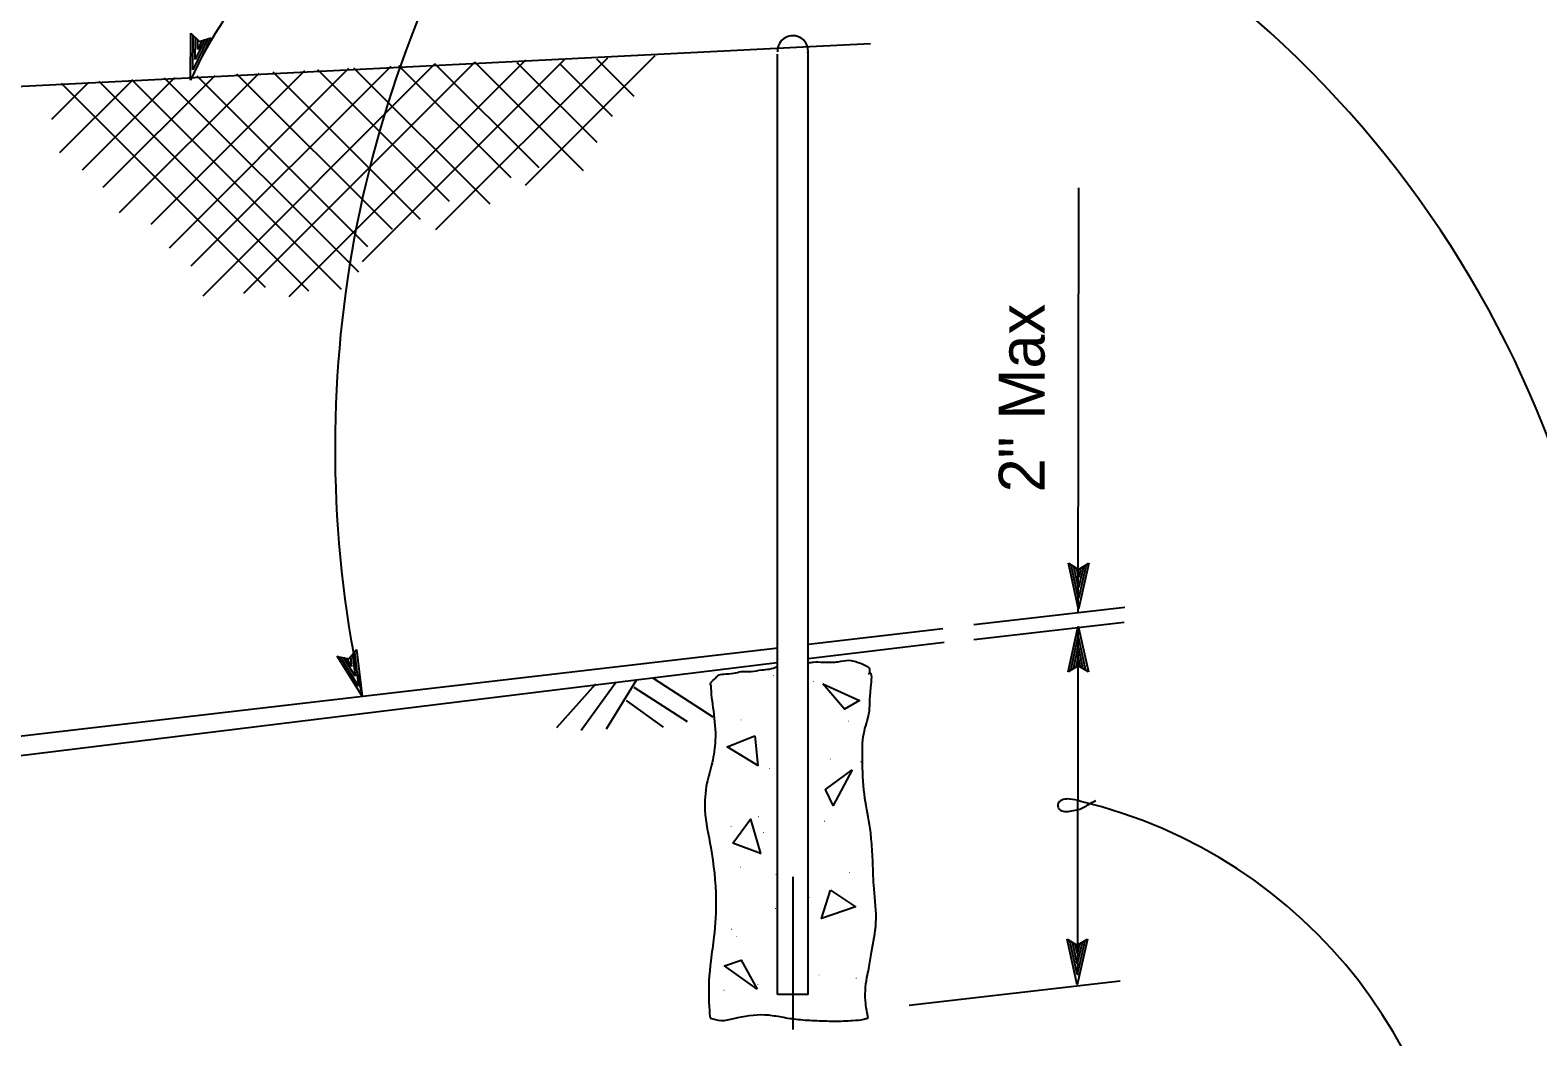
# Model space of a CAD drawing. Extents: x 6710407 to 6714861, y 1868090 to 1871317.
# Drawn here: x 6711941.5 to 6712138.9, y 1870342.8 to 1870474.7 of the extents above; entities that cross this region are included whole.
import ezdxf

# ---------------------------------------------------------------- set-up
doc = ezdxf.new("R2010")
doc.units = 0
for name, color, linetype in [('G-MARK', 7, 'Continuous'), ('G-TEXT', 7, 'Continuous'), ('Nongeo Data(60)', 7, 'Continuous')]:
    doc.layers.add(name, color=color, linetype=linetype)

msp = doc.modelspace()

# ---------------------------------------------------------------- linework, layer by layer
at = {"layer": 'G-MARK'}
for p, q in [((6712078.74, 1870398.4), (6712078.79, 1870454.09)), ((6712065.04, 1870396.85), (6712084.83, 1870399.15)), ((6712065.05, 1870394.89), (6712084.76, 1870397.18)), ((6712078.69, 1870350.91), (6712078.73, 1870396.57)), ((6712056.59, 1870346.99), (6712084.22, 1870350.2))]:
    msp.add_line(p, q, dxfattribs=at)
msp.add_lwpolyline([(6712041.34, 1870363.81), (6712041.34, 1870343.81)], dxfattribs=at)
for centre, radius, start, end in [((6712013, 1870445.19), 55.53, 98.9217, 155.5531), ((6712132.22, 1870419.98), 150.83, 147.9377, 192.4445), ((6712010.63, 1870371.44), 138.89, 1.0544, 66.3616), ((6712063.9, 1870310.34), 65.14, 358.9398, 76.5372)]:
    msp.add_arc(centre, radius, start, end, dxfattribs=at)
msp.add_spline([(6712079.07, 1870373.69), (6712077.59, 1870374), (6712076.75, 1870373.92), (6712076.17, 1870373.54), (6712076.09, 1870372.92), (6712076.26, 1870372.63), (6712076.92, 1870372.38), (6712077.88, 1870372.46), (6712078.75, 1870372.63), (6712079.46, 1870372.92), (6712080.16, 1870373.34), (6712081.04, 1870373.79)], degree=3, dxfattribs=at)
at = {"layer": 'G-TEXT'}
for p, q in [((6711962.46, 1870468.17), (6711962.52, 1870474.32)), ((6711962.52, 1870474.32), (6711962.52, 1870474.32)), ((6711962.52, 1870474.32), (6711963.63, 1870473.24)), ((6711965.12, 1870473.71), (6711962.46, 1870468.17)), ((6711962.77, 1870469.53), (6711962.81, 1870474.01)), ((6711964.72, 1870473.58), (6711962.77, 1870469.51)), ((6711963.08, 1870470.86), (6711963.11, 1870473.75)), ((6711964.32, 1870473.44), (6711963.08, 1870470.86)), ((6711963.4, 1870472.21), (6711963.41, 1870473.44)), ((6711963.94, 1870473.34), (6711963.4, 1870472.21)), ((6711963.63, 1870473.24), (6711965.12, 1870473.71)), ((6711965.12, 1870473.71), (6711965.12, 1870473.71)), ((6711962.46, 1870468.17), (6711962.46, 1870468.17)), ((6712078.78, 1870398.89), (6712077.45, 1870404.89)), ((6712077.45, 1870404.89), (6712077.45, 1870404.89)), ((6712077.45, 1870404.89), (6712078.78, 1870404.09)), ((6712078.78, 1870400.28), (6712077.81, 1870404.66)), ((6712078.78, 1870401.65), (6712078.16, 1870404.48)), ((6712078.79, 1870403.03), (6712078.52, 1870404.24)), ((6712078.78, 1870404.09), (6712080.12, 1870404.89)), ((6712080.12, 1870404.89), (6712078.78, 1870398.89)), ((6712079.77, 1870404.67), (6712078.78, 1870400.27)), ((6712079.41, 1870404.44), (6712078.78, 1870401.65)), ((6712079.06, 1870404.26), (6712078.79, 1870403.03)), ((6712080.12, 1870404.89), (6712080.12, 1870404.89)), ((6712078.78, 1870398.89), (6712078.78, 1870398.89)), ((6712077.39, 1870390.66), (6712078.73, 1870396.66)), ((6712077.74, 1870390.87), (6712078.73, 1870395.28)), ((6712078.73, 1870396.66), (6712078.73, 1870396.66)), ((6712078.73, 1870396.66), (6712080.06, 1870390.66)), ((6712078.74, 1870395.27), (6712079.7, 1870390.89)), ((6711983.21, 1870392.38), (6711984.21, 1870393.58)), ((6711983.95, 1870393.26), (6711984.48, 1870388.77)), ((6711984.21, 1870393.58), (6711984.21, 1870393.58)), ((6711984.21, 1870393.58), (6711984.93, 1870387.47)), ((6712078.1, 1870391.11), (6712078.73, 1870393.89)), ((6712078.73, 1870393.89), (6712079.35, 1870391.07)), ((6711984.93, 1870387.47), (6711981.69, 1870392.7)), ((6711981.69, 1870392.69), (6711981.69, 1870392.69)), ((6711981.69, 1870392.69), (6711983.21, 1870392.38)), ((6711984.47, 1870388.78), (6711982.11, 1870392.59)), ((6711984.02, 1870390.08), (6711982.49, 1870392.54)), ((6711983.56, 1870391.38), (6711982.91, 1870392.44)), ((6711983.42, 1870392.63), (6711983.56, 1870391.38)), ((6711983.69, 1870392.92), (6711984.02, 1870390.08)), ((6712078.73, 1870391.46), (6712077.39, 1870390.66)), ((6712078.45, 1870391.28), (6712078.73, 1870392.51)), ((6712078.73, 1870392.51), (6712078.99, 1870391.3)), ((6712080.06, 1870390.66), (6712078.73, 1870391.46)), ((6712077.39, 1870390.66), (6712077.39, 1870390.66)), ((6712080.06, 1870390.66), (6712080.06, 1870390.66)), ((6711984.93, 1870387.47), (6711984.93, 1870387.47)), ((6712078.6, 1870349.65), (6712077.27, 1870355.65)), ((6712077.27, 1870355.65), (6712077.27, 1870355.65)), ((6712077.27, 1870355.65), (6712078.6, 1870354.85)), ((6712078.6, 1870351.04), (6712077.63, 1870355.41)), ((6712078.6, 1870352.41), (6712077.98, 1870355.24)), ((6712078.61, 1870353.79), (6712078.34, 1870355)), ((6712078.6, 1870354.85), (6712079.94, 1870355.65)), ((6712079.94, 1870355.65), (6712078.6, 1870349.65)), ((6712079.59, 1870355.43), (6712078.6, 1870351.03)), ((6712079.23, 1870355.2), (6712078.6, 1870352.41)), ((6712078.88, 1870355.02), (6712078.61, 1870353.79)), ((6712079.94, 1870355.65), (6712079.94, 1870355.65)), ((6712078.6, 1870349.65), (6712078.6, 1870349.65))]:
    msp.add_line(p, q, dxfattribs=at)
at = {"layer": 'Nongeo Data(60)'}
for p, q in [((6711874.34, 1870464.05), (6712043.57, 1870472.58)), ((6712043.57, 1870472.58), (6712051.52, 1870472.98)), ((6711964.1, 1870439.93), (6711994.48, 1870470.31)), ((6711969.44, 1870440.29), (6711999.7, 1870470.55)), ((6711975.37, 1870439.82), (6712006.38, 1870470.82)), ((6711984.98, 1870444.44), (6712011.48, 1870470.94)), ((6712008.12, 1870456.67), (6711994.48, 1870470.31)), ((6711994.59, 1870448.6), (6712017.12, 1870471.12)), ((6712013.94, 1870456.31), (6711999.7, 1870470.55)), ((6712015.72, 1870459.99), (6712005.26, 1870470.45)), ((6712006.34, 1870454.41), (6712023.32, 1870471.39)), ((6712017.73, 1870463.43), (6712010.85, 1870470.31)), ((6712020.58, 1870466.04), (6712015.7, 1870470.93)), ((6712039.34, 1870394.15), (6712039.34, 1870471.56)), ((6712043.34, 1870394.27), (6712043.34, 1870472)), ((6711948.31, 1870456.43), (6711960.41, 1870468.53)), ((6711951.04, 1870454.17), (6711965.67, 1870468.8)), ((6711953.18, 1870450.85), (6711971.44, 1870469.11)), ((6711957.33, 1870449.31), (6711977.45, 1870469.43)), ((6711984.51, 1870443.02), (6711959.07, 1870468.45)), ((6711959.71, 1870446.22), (6711983.21, 1870469.73)), ((6711962.55, 1870443.85), (6711988.73, 1870470.02)), ((6711985.69, 1870446.34), (6711963.35, 1870468.68)), ((6711988.9, 1870448.6), (6711968.54, 1870468.95)), ((6711992.58, 1870449.9), (6711973.27, 1870469.2)), ((6711996.37, 1870452.28), (6711979.13, 1870469.51)), ((6712001.71, 1870451.92), (6711983.87, 1870469.76)), ((6712004.44, 1870455.36), (6711989.73, 1870470.07)), ((6711944.28, 1870463.07), (6711949.13, 1870467.93)), ((6711945.35, 1870458.68), (6711954.9, 1870468.23)), ((6711972.28, 1870441), (6711945.55, 1870467.74)), ((6711977.98, 1870440.53), (6711950.51, 1870468)), ((6711982.25, 1870440.76), (6711954.79, 1870468.23)), ((6712043.39, 1870394.27), (6712061.01, 1870396.32)), ((6711874.36, 1870374.61), (6712039.44, 1870393.81)), ((6712039.34, 1870348.39), (6712039.34, 1870394.1)), ((6712043.34, 1870348.39), (6712043.34, 1870394.36)), ((6712043.36, 1870392.39), (6712061.15, 1870394.57)), ((6711874.31, 1870371.63), (6712039.3, 1870391.89)), ((6712018.22, 1870389.32), (6712013.61, 1870382.99)), ((6712020.87, 1870389.62), (6712016.88, 1870383.14)), ((6712023.05, 1870389.84), (6712030.89, 1870384.77)), ((6712015.49, 1870389.04), (6712010.41, 1870383.35)), ((6712014.31, 1870388.64), (6712014.31, 1870388.64)), ((6712020.51, 1870388.67), (6712027.52, 1870384.14)), ((6712019.53, 1870386.9), (6712024.35, 1870383.42)), ((6712043.34, 1870348.39), (6712039.34, 1870348.39))]:
    msp.add_line(p, q, dxfattribs=at)
for points in [[(6712045.29, 1870389.08), (6712050.1, 1870386.93), (6712048.1, 1870385.77)], [(6712036.36, 1870382.28), (6712036.76, 1870378.4), (6712032.74, 1870380.85)], [(6712049.11, 1870377.82), (6712046.64, 1870373.17), (6712045.61, 1870375.25)], [(6712033.48, 1870368.24), (6712035.8, 1870371.38), (6712037.12, 1870366.86)], [(6712046.3, 1870362.05), (6712049.56, 1870359.89), (6712045.12, 1870358.35)], [(6712036.68, 1870349.08), (6712032.39, 1870352.13), (6712034.58, 1870352.88)]]:
    msp.add_lwpolyline(points, close=True, dxfattribs=at)
msp.add_arc((6712041.34, 1870472), 2, 352.4216, 183.1965, dxfattribs=at)
for points in [[(6712030.6, 1870388.94), (6712030.56, 1870389.07), (6712031.1, 1870389.72), (6712031.53, 1870390.16), (6712032.3, 1870390.38), (6712033.6, 1870390.48), (6712034.58, 1870390.7), (6712035.88, 1870390.7), (6712037.29, 1870390.92), (6712038.27, 1870391.03), (6712039.36, 1870391.35)], [(6712051.4, 1870390.46), (6712051.42, 1870391.03), (6712050.87, 1870391.46), (6712049.79, 1870391.9), (6712049.03, 1870392.11), (6712047.61, 1870392.01), (6712046.85, 1870391.9), (6712045.87, 1870391.9), (6712045.33, 1870391.9), (6712044.03, 1870391.9), (6712043.38, 1870391.79)], [(6712051.2, 1870345.31), (6712050.89, 1870347.18), (6712051.06, 1870350.63), (6712051.31, 1870351.81), (6712051.65, 1870353.92), (6712052.24, 1870357.79), (6712051.98, 1870362.25), (6712051.82, 1870365.71), (6712051.65, 1870368.48), (6712051.4, 1870370.67), (6712050.72, 1870374.63), (6712050.47, 1870379.26), (6712050.64, 1870382.55), (6712051.31, 1870385.16), (6712051.56, 1870388.61), (6712051.4, 1870390.46), (6712051.2, 1870390.31)], [(6712030.6, 1870388.97), (6712030.6, 1870388.94), (6712030.94, 1870385.58), (6712031.19, 1870381.7), (6712030.77, 1870378.76), (6712030.09, 1870376.06), (6712029.84, 1870372.53), (6712030.6, 1870367.64), (6712031.27, 1870360.91), (6712031.02, 1870355.94), (6712030.6, 1870352.82), (6712030.35, 1870347.52), (6712030.5, 1870345.31)], [(6712030.5, 1870345.31), (6712031.95, 1870344.99), (6712033.63, 1870345.25), (6712037.67, 1870345.75), (6712039.61, 1870345.5), (6712041.8, 1870345.16), (6712044.15, 1870344.99), (6712046.76, 1870344.91), (6712049.21, 1870344.99), (6712050.64, 1870345.16), (6712051.2, 1870345.31)]]:
    msp.add_spline(points, degree=3, dxfattribs=at)

# ---------------------------------------------------------------- texts
for s, height, rotation, p in [('2" Max', 6, 90, (6712074.32, 1870414.17)), ('.', 0.8, 280.1715, (6712038.74, 1870390.29)), ('.', 0.8, 88.8366, (6712044.12, 1870389.27)), ('.', 0.8, 88.8366, (6712034.62, 1870384.22)), ('.', 0.8, 186.2875, (6712048.75, 1870384.29)), ('.', 0.8, 266.9315, (6712038.23, 1870378.18)), ('.', 0.8, 266.9315, (6712046.23, 1870379.4)), ('.', 0.8, 88.8366, (6712050.3, 1870378.73)), ('.', 0.8, 186.2875, (6712037, 1870371.74)), ('.', 0.8, 266.9315, (6712033.22, 1870370.57)), ('.', 0.8, 88.8366, (6712037.58, 1870369.46)), ('.', 0.8, 88.8366, (6712045.54, 1870370.95)), ('.', 0.8, 354.002, (6712051.47, 1870368.07)), ('.', 0.8, 186.2875, (6712034.61, 1870365.16)), ('.', 0.8, 354.002, (6712038.99, 1870364.05)), ('.', 0.8, 266.9315, (6712048.7, 1870364.55)), ('.', 0.8, 266.9315, (6712039.04, 1870359.82)), ('.', 0.8, 88.8366, (6712043.54, 1870360.93)), ('.', 0.8, 354.002, (6712033.16, 1870356.89)), ('.', 0.8, 88.8366, (6712034.05, 1870355.88)), ('.', 0.8, 354.002, (6712043.22, 1870354.16)), ('.', 0.8, 266.9315, (6712044.72, 1870351.1)), ('.', 0.8, 88.8366, (6712049.72, 1870350.39)), ('.', 0.8, 354.002, (6712032.2, 1870348.9)), ('.', 0.8, 266.9315, (6712036.71, 1870349.88)), ('.', 0.8, 354.002, (6712044.99, 1870344.89))]:
    msp.add_text(s, height=height, rotation=rotation, dxfattribs=at).set_placement(p)
msp.add_text('.', height=0.36, dxfattribs=at).set_placement((6712043.4, 1870391.79))

doc.saveas('drawing.dxf')
